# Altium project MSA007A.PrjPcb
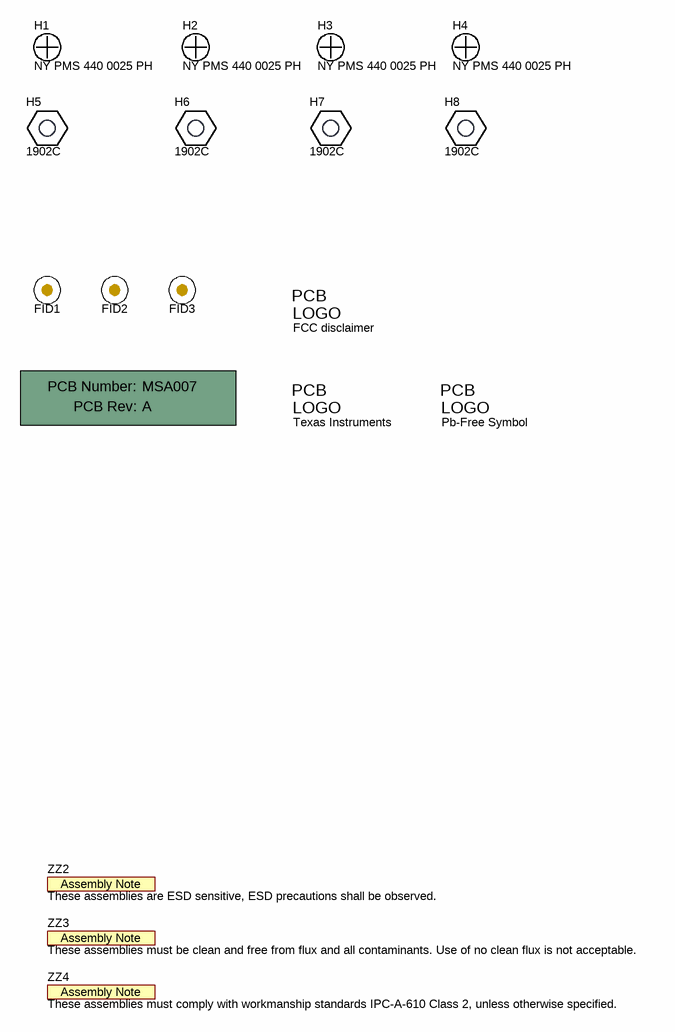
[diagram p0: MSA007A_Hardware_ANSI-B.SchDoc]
CopyrightYear: 2015; PCB_Layout: Alex Wang; PCB_Rev: A; PRJ_Customer: Public Release; PRJ_Engineer: Alex Wang; PRJ_Number: MSA007; PRJ_Title: TPS4H160EVM; SCH_Rev: A; TechSupport: http://www.ti.com/support
2 sheets, 129 parts. Net scope: global (net labels, ports and power ports of the same name join across sheets).
Board file: MSA007A.PcbDoc
Sheets:
  MSA007A_Hardware_ANSI-B.SchDoc
  MSA007A.SchDoc

## Sheet MSA007A_Hardware_ANSI-B.SchDoc
size 431 x 279 mm; Date: Not shown in title block; ApprovedBy: Not shown in title block; CheckedBy: Not shown in title block; Author: Not shown in title block; CompanyName: Not shown in title block; Engineer: Not shown in title block; Organization: Not shown in title block; Address1: Not shown in title block; Address2: Not shown in title block; Address3: Not shown in title block; Address4: Not shown in title block; DocumentNumber: 1; Revision: Use project parameter SCH_Rev; SheetNumber: 1; SheetTotal: 1; PageSetup: Record=PageOptions¦CenterHorizontal=True¦CenterVertical=True¦PrintScale=1.00¦XCorrection=1.00¦YCorrection=1.00¦PrintKind=0¦BorderSize=5000000¦LeftOffset=0¦BottomOffset=0¦Orientation=2¦PaperLength=1000¦PaperWidth=1000¦Scale=100¦PaperSource=15¦PrintQuality=600¦MediaType=1¦DitherType=10¦PaperKind=Letter¦PrintScaleMode=1

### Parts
!PCB1  Printed Circuit Board  (value not drawn)  (mechanical)
FID1  Fiducial  [Fiducial10-20]  (value not drawn)
FID2  Fiducial  [Fiducial10-20]  (value not drawn)
FID3  Fiducial  [Fiducial10-20]  (value not drawn)
H1  NY PMS 440 0025 PH  [NY PMS 440 0025 PH]
H2  NY PMS 440 0025 PH  [NY PMS 440 0025 PH]
H3  NY PMS 440 0025 PH  [NY PMS 440 0025 PH]
H4  NY PMS 440 0025 PH  [NY PMS 440 0025 PH]
H5  1902C  [Keystone_1902C]
H6  1902C  [Keystone_1902C]
H7  1902C  [Keystone_1902C]
H8  1902C  [Keystone_1902C]
Logo1  Texas Instruments  [TI_Stacked_Overlay_Medium]  (no BOM)
Logo2  Pb-Free Symbol  [Pb-Free_Overlay_Small]  (no BOM)
Logo3  FCC disclaimer  [FCC_disclaimer]  (no BOM)
ZZ2  These assemblies are ESD sensitive, ESD precautions shall be observed.  [AssemblyNote]  (no BOM)
ZZ3  These assemblies must be clean and free from flux and all contaminants. Use of no clean flux is not acceptable.  [AssemblyNote]  (no BOM)
ZZ4  These assemblies must comply with workmanship standards IPC-A-610 Class 2, unless otherwise specified.  [AssemblyNote]  (no BOM)

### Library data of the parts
!PCB1 = PCB: Manufacturer: Any; PartNumber: MSA007; SymbolCreator: a0412235
FID1-FID3 = Fiducial: Fiducial mark.  There is nothing to buy or mount.; SymbolCreator: codlsc
H1-H4 = NY PMS 440 0025 PH: Machine Screw, Round, #4-40 x 1/4, Nylon, Philips panhead; Manufacturer: B&F Fastener Supply; CompType: Hardware; SymbolCreator: codlsc; U/M: EA
H5-H8 = 1902C: Standoff, Hex, 0.5"L #4-40 Nylon; Manufacturer: Keystone; CompType: Hardware; SymbolCreator: a0412235
Logo1 = TI_Logo: Texas Instrument Corporate Signature; SymbolCreator: a0412235
Logo2 = Pb-Free: SymbolCreator: a0412235
Logo3 = FCC_disclaimer: SymbolCreator: codlsc
ZZ2-ZZ4 = AssemblyNote: SymbolCreator: codlsc

## Sheet MSA007A.SchDoc
size A2; Date: Not shown in title block; ApprovedBy: Not shown in title block; CheckedBy: Not shown in title block; Author: Not shown in title block; CompanyName: Not shown in title block; DrawnBy: Alex Wang; Engineer: Not shown in title block; Organization: Not shown in title block; Address1: Not shown in title block; Address2: Not shown in title block; Address3: Not shown in title block; Address4: Not shown in title block; DocumentNumber: 1; Revision: Use project parameter SCH_Rev; SheetNumber: 1; SheetTotal: 1; PageSetup: Record=PageOptions¦CenterHorizontal=True¦CenterVertical=True¦PrintScale=0.47¦XCorrection=1.00¦YCorrection=1.00¦PrintKind=0¦BorderSize=5000000¦LeftOffset=0¦BottomOffset=0¦Orientation=2¦PaperLength=1000¦PaperWidth=1000¦Scale=100¦PaperSource=15¦PrintQuality=600¦MediaType=1¦DitherType=10¦PaperKind=Letter¦PrintScaleMode=1
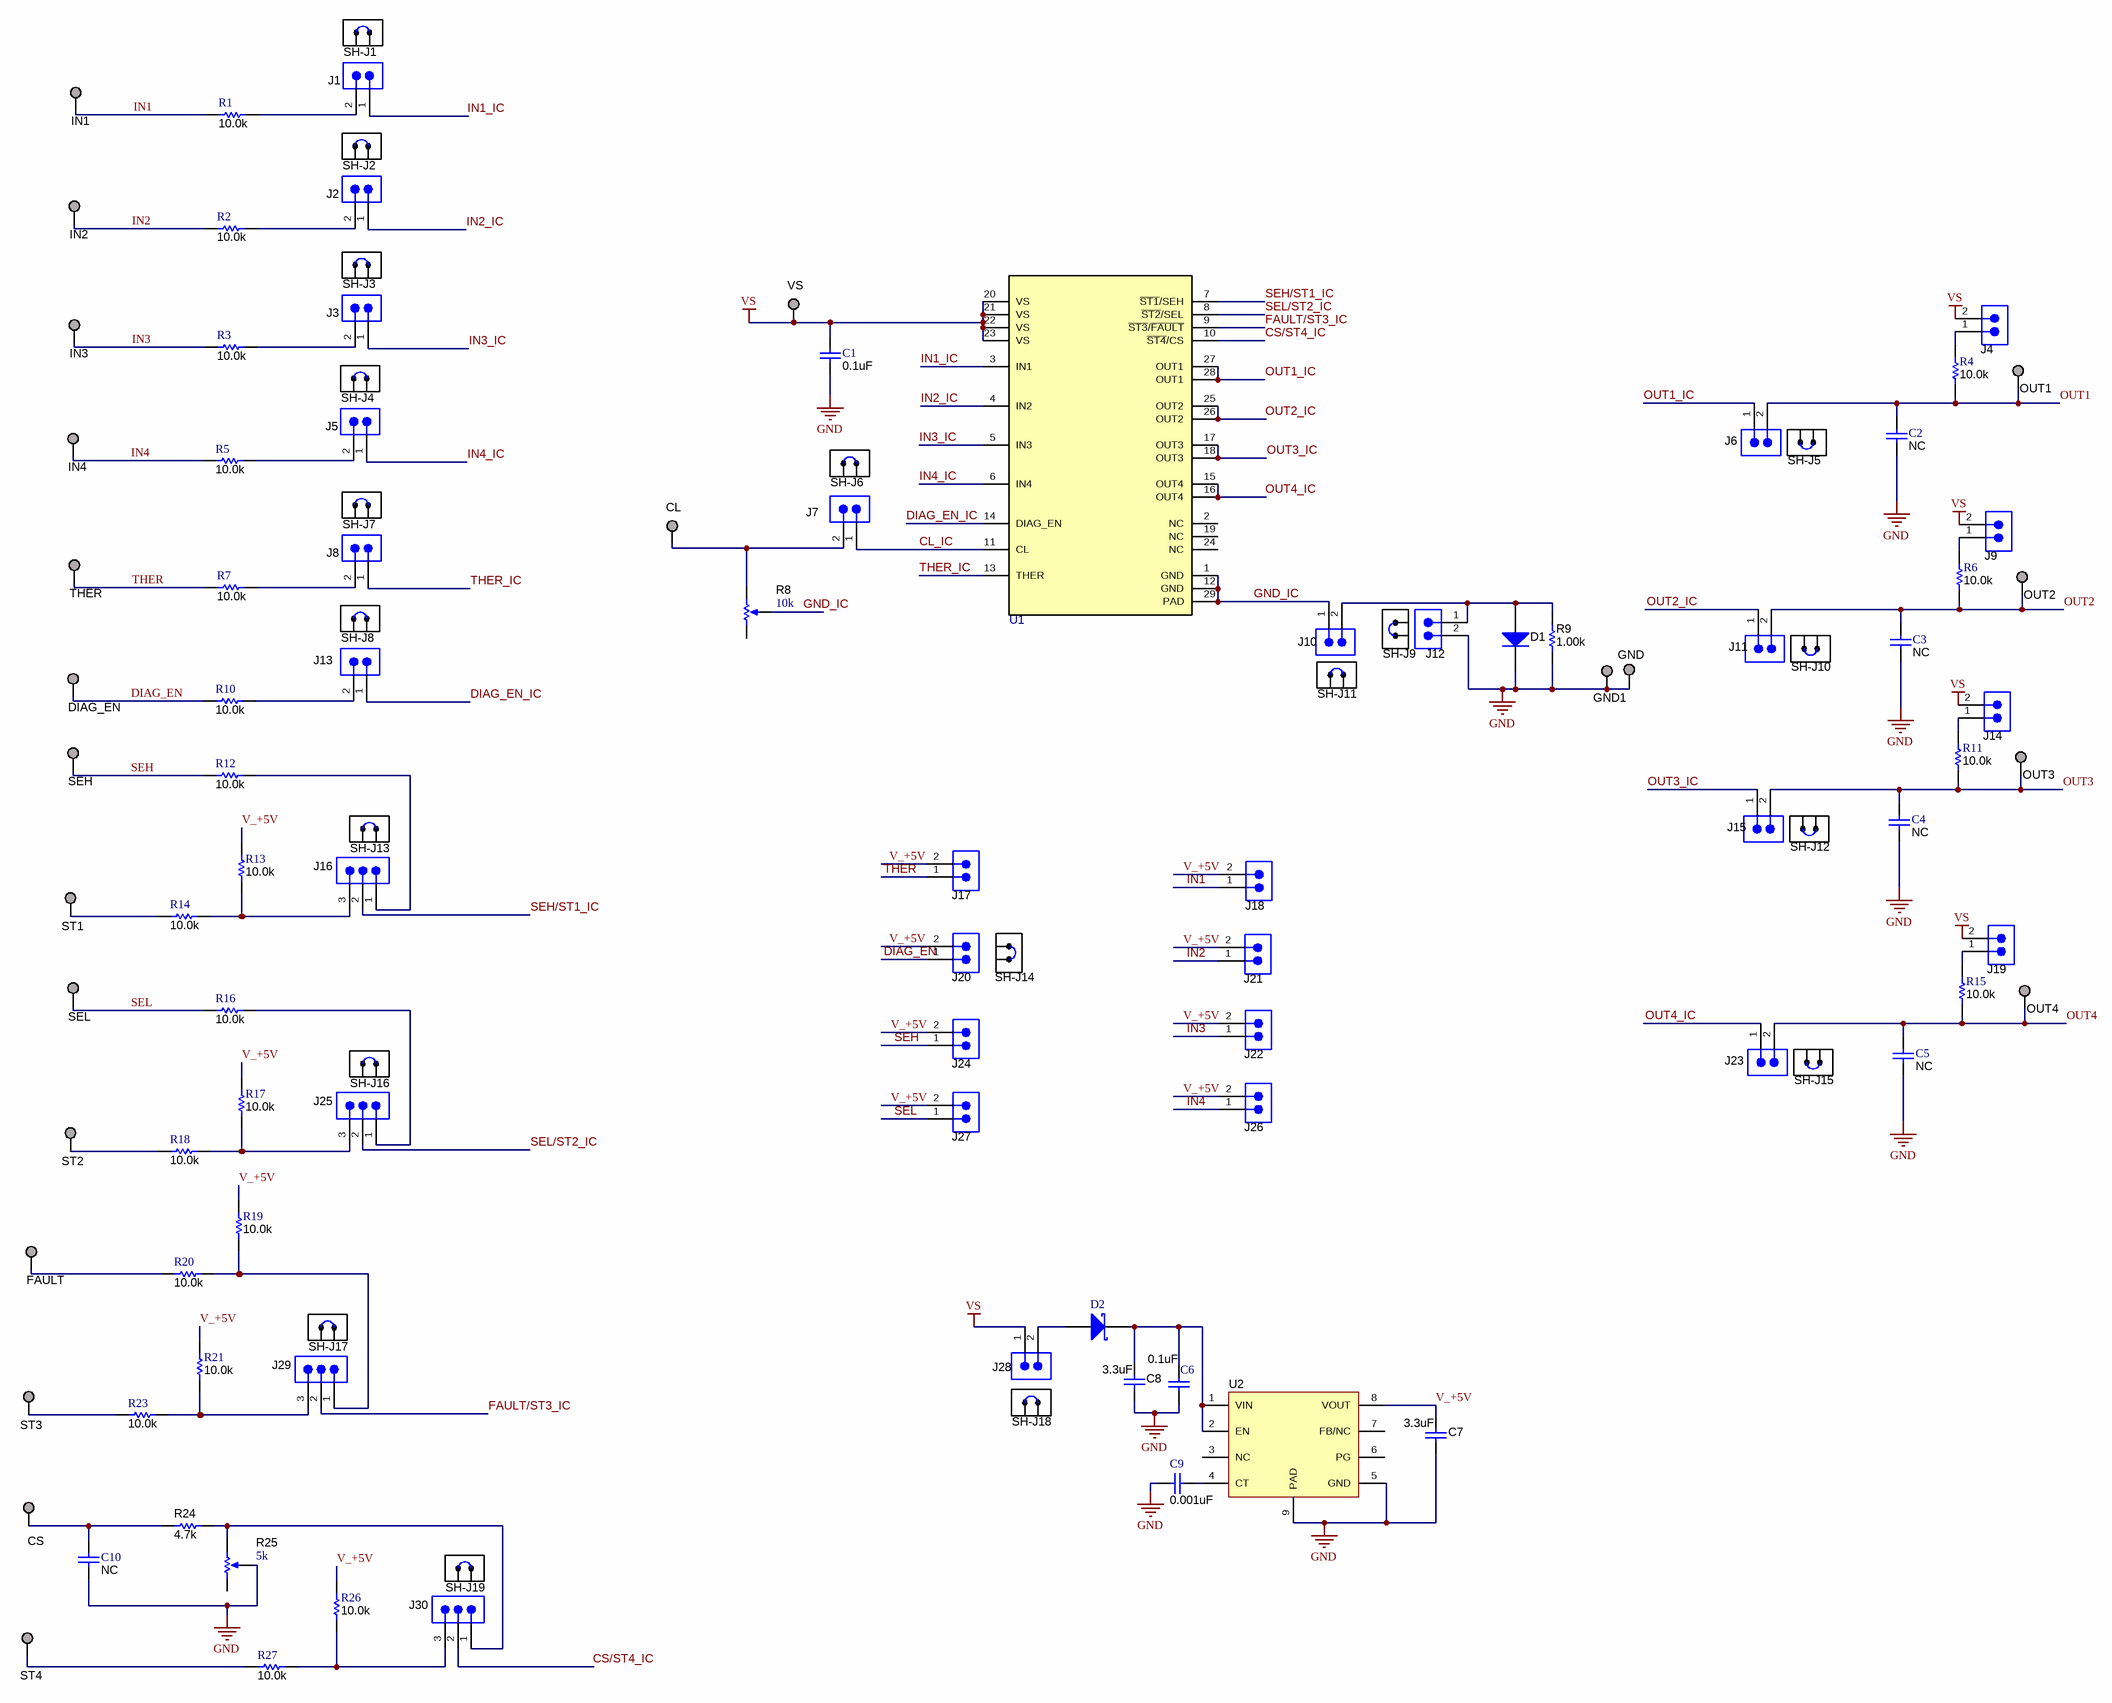
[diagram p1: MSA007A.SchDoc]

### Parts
C1  ValueDisplayed: 0.1uF  [0603]  (hidden comment: GRM188R71H104KA93D)
C2  08051C103JAT2A  [0805_HV]  (value not drawn)
C3  08051C103JAT2A  [0805_HV]  (value not drawn)
C4  08051C103JAT2A  [0805_HV]  (value not drawn)
C5  08051C103JAT2A  [0805_HV]  (value not drawn)
C6  ValueDisplayed: 0.1uF  [0603]  (hidden comment: GRM188R71H104KA93D)
C7  ValueDisplayed: 3.3uF  [1210]  (hidden comment: C3225X7R1H335M)
C8  ValueDisplayed: 3.3uF  [1210]  (hidden comment: C3225X7R1H335M)
C9  ValueDisplayed: 0.001uF  [0603]  (hidden comment: 06035A102KAT2A)
C10  ValueDisplayed: NC  [0603]  (hidden comment: GRM188R71H104KA93D)
CL  Suggest using a net name here  [Keystone1502-2]  (value not drawn)
CS  Suggest using a net name here  [Keystone1502-2]  (value not drawn)
D1  BAS21-7-F  [SOT-23]  (value not drawn)
D2  B150-13-F  [SMA]  (value not drawn)
DIAG_EN  Suggest using a net name here  [Keystone1502-2]  (value not drawn)
FAULT  Suggest using a net name here  [Keystone1502-2]  (value not drawn)
GND  Suggest using a net name here  [Keystone1502-2]  (value not drawn)
GND1  GND  [Keystone1502-2]  (value not drawn)
IN1  Suggest using a net name here  [Keystone1502-2]  (value not drawn)
IN2  Suggest using a net name here  [Keystone1502-2]  (value not drawn)
IN3  Suggest using a net name here  [Keystone1502-2]  (value not drawn)
IN4  Suggest using a net name here  [Keystone1502-2]  (value not drawn)
J1  TSW-102-07-G-S  [TSW-102-07-G-S]  (value not drawn)
J2  TSW-102-07-G-S  [TSW-102-07-G-S]  (value not drawn)
J3  TSW-102-07-G-S  [TSW-102-07-G-S]  (value not drawn)
J4  TSW-102-07-G-S  [TSW-102-07-G-S]  (value not drawn)
J5  TSW-102-07-G-S  [TSW-102-07-G-S]  (value not drawn)
J6  TSW-102-07-G-S  [TSW-102-07-G-S]  (value not drawn)
J7  TSW-102-07-G-S  [TSW-102-07-G-S]  (value not drawn)
J8  TSW-102-07-G-S  [TSW-102-07-G-S]  (value not drawn)
J9  TSW-102-07-G-S  [TSW-102-07-G-S]  (value not drawn)
J10  TSW-102-07-G-S  [TSW-102-07-G-S]  (value not drawn)
J11  TSW-102-07-G-S  [TSW-102-07-G-S]  (value not drawn)
J12  TSW-102-07-G-S  [TSW-102-07-G-S]  (value not drawn)
J13  TSW-102-07-G-S  [TSW-102-07-G-S]  (value not drawn)
J14  TSW-102-07-G-S  [TSW-102-07-G-S]  (value not drawn)
J15  TSW-102-07-G-S  [TSW-102-07-G-S]  (value not drawn)
J16  TSW-103-07-G-S  [TSW-103-07-G-S]  (value not drawn)
J17  TSW-102-07-G-S  [TSW-102-07-G-S]  (value not drawn)
J18  TSW-102-07-G-S  [TSW-102-07-G-S]  (value not drawn)
J19  TSW-102-07-G-S  [TSW-102-07-G-S]  (value not drawn)
J20  TSW-102-07-G-S  [TSW-102-07-G-S]  (value not drawn)
J21  TSW-102-07-G-S  [TSW-102-07-G-S]  (value not drawn)
J22  TSW-102-07-G-S  [TSW-102-07-G-S]  (value not drawn)
J23  TSW-102-07-G-S  [TSW-102-07-G-S]  (value not drawn)
J24  TSW-102-07-G-S  [TSW-102-07-G-S]  (value not drawn)
J25  TSW-103-07-G-S  [TSW-103-07-G-S]  (value not drawn)
J26  TSW-102-07-G-S  [TSW-102-07-G-S]  (value not drawn)
J27  TSW-102-07-G-S  [TSW-102-07-G-S]  (value not drawn)
J28  TSW-102-07-G-S  [TSW-102-07-G-S]  (value not drawn)
J29  TSW-103-07-G-S  [TSW-103-07-G-S]  (value not drawn)
J30  TSW-103-07-G-S  [TSW-103-07-G-S]  (value not drawn)
OUT1  Suggest using a net name here  [Keystone1502-2]  (value not drawn)
OUT2  Suggest using a net name here  [Keystone1502-2]  (value not drawn)
OUT3  Suggest using a net name here  [Keystone1502-2]  (value not drawn)
OUT4  Suggest using a net name here  [Keystone1502-2]  (value not drawn)
R1  value 10.0k  [0603]  (hidden comment: CRCW060310K0FKEA)
R2  value 10.0k  [0603]  (hidden comment: CRCW060310K0FKEA)
R3  value 10.0k  [0603]  (hidden comment: CRCW060310K0FKEA)
R4  value 10.0k  [0603]  (hidden comment: CRCW060310K0FKEA)
R5  value 10.0k  [0603]  (hidden comment: CRCW060310K0FKEA)
R6  value 10.0k  [0603]  (hidden comment: CRCW060310K0FKEA)
R7  value 10.0k  [0603]  (hidden comment: CRCW060310K0FKEA)
R8  value 10k  [BOURNS_3386P]  (hidden comment: 3386P-1-103LF)
R9  value 1.00k  [0805_HV]  (hidden comment: CRCW08051K00FKEA)
R10  value 10.0k  [0603]  (hidden comment: CRCW060310K0FKEA)
R11  value 10.0k  [0603]  (hidden comment: CRCW060310K0FKEA)
R12  value 10.0k  [0603]  (hidden comment: CRCW060310K0FKEA)
R13  value 10.0k  [0603]  (hidden comment: CRCW060310K0FKEA)
R14  value 10.0k  [0603]  (hidden comment: CRCW060310K0FKEA)
R15  value 10.0k  [0603]  (hidden comment: CRCW060310K0FKEA)
R16  value 10.0k  [0603]  (hidden comment: CRCW060310K0FKEA)
R17  value 10.0k  [0603]  (hidden comment: CRCW060310K0FKEA)
R18  value 10.0k  [0603]  (hidden comment: CRCW060310K0FKEA)
R19  value 10.0k  [0603]  (hidden comment: CRCW060310K0FKEA)
R20  value 10.0k  [0603]  (hidden comment: CRCW060310K0FKEA)
R21  value 10.0k  [0603]  (hidden comment: CRCW060310K0FKEA)
R23  value 10.0k  [0603]  (hidden comment: CRCW060310K0FKEA)
R24  value 4.7k  [0603]  (hidden comment: CRCW06034K70JNEA)
R25  value 5k  [BOURNS_3386P]  (hidden comment: 3386P-1-502LF)
R26  value 10.0k  [0603]  (hidden comment: CRCW060310K0FKEA)
R27  value 10.0k  [0603]  (hidden comment: CRCW060310K0FKEA)
SEH  Suggest using a net name here  [Keystone1502-2]  (value not drawn)
SEL  Suggest using a net name here  [Keystone1502-2]  (value not drawn)
SH-J1  969102-0000-DA  [SNT-100-BK-G]  (value not drawn)
SH-J2  969102-0000-DA  [SNT-100-BK-G]  (value not drawn)
SH-J3  969102-0000-DA  [SNT-100-BK-G]  (value not drawn)
SH-J4  969102-0000-DA  [SNT-100-BK-G]  (value not drawn)
SH-J5  969102-0000-DA  [SNT-100-BK-G]  (value not drawn)
SH-J6  969102-0000-DA  [SNT-100-BK-G]  (value not drawn)
SH-J7  969102-0000-DA  [SNT-100-BK-G]  (value not drawn)
SH-J8  969102-0000-DA  [SNT-100-BK-G]  (value not drawn)
SH-J9  969102-0000-DA  [SNT-100-BK-G]  (value not drawn)
SH-J10  969102-0000-DA  [SNT-100-BK-G]  (value not drawn)
SH-J11  969102-0000-DA  [SNT-100-BK-G]  (value not drawn)
SH-J12  969102-0000-DA  [SNT-100-BK-G]  (value not drawn)
SH-J13  969102-0000-DA  [SNT-100-BK-G]  (value not drawn)
SH-J14  969102-0000-DA  [SNT-100-BK-G]  (value not drawn)
SH-J15  969102-0000-DA  [SNT-100-BK-G]  (value not drawn)
SH-J16  969102-0000-DA  [SNT-100-BK-G]  (value not drawn)
SH-J17  969102-0000-DA  [SNT-100-BK-G]  (value not drawn)
SH-J18  969102-0000-DA  [SNT-100-BK-G]  (value not drawn)
SH-J19  969102-0000-DA  [SNT-100-BK-G]  (value not drawn)
ST1  Suggest using a net name here  [Keystone1502-2]  (value not drawn)
ST2  Suggest using a net name here  [Keystone1502-2]  (value not drawn)
ST3  Suggest using a net name here  [Keystone1502-2]  (value not drawn)
ST4  Suggest using a net name here  [Keystone1502-2]  (value not drawn)
THER  Suggest using a net name here  [Keystone1502-2]  (value not drawn)
U1  TPS4H160BQPWPRQ1  [PWP0028C_N]  (value not drawn)
U2  TPS7A6650QDGNRQ1  [DGN0008D_N]  (value not drawn)
VS  Suggest using a net name here  [Keystone1502-2]  (value not drawn)

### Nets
GND: C1.1 C2.2 C3.2 C4.2 C5.2 C6.1 C7.2 C8.2 C9.1 C10.2 D1.3(K) GND.1 GND1.1 J12.2 R9.2 R25.2(WIPER) U2.5(GND) U2.9(PAD)
VS: C1.2 J4.2 J9.2 J14.2 J19.2 J28.1 U1.20(VS) U1.21(VS) U1.22(VS) U1.23(VS) VS.1
CL_IC: J7.1 U1.11(CL)
CS/ST4_IC: J30.2 U1.10(~{ST4}/CS)
DIAG_EN: DIAG_EN.1 J20.1 R10.2
DIAG_EN_IC: J13.1 U1.14(DIAG_EN)
FAULT/ST3_IC: J29.2 U1.9(~{ST3}/~{FAULT})
GND_IC: J10.1 R8.2(WIPER) U1.1(GND) U1.12(GND) U1.29(PAD)
IN1: IN1.1 J18.1 R1.2
IN1_IC: J1.1 U1.3(IN1)
IN2: IN2.1 J21.1 R2.2
IN2_IC: J2.1 U1.4(IN2)
IN3: IN3.1 J22.1 R3.2
IN3_IC: J3.1 U1.5(IN3)
IN4: IN4.1 J26.1 R5.2
IN4_IC: J5.1 U1.6(IN4)
OUT1: C2.1 J6.2 OUT1.1 R4.1
OUT1_IC: J6.1 U1.27(OUT1) U1.28(OUT1)
OUT2: C3.1 J11.2 OUT2.1 R6.1
OUT2_IC: J11.1 U1.25(OUT2) U1.26(OUT2)
OUT3: C4.1 J15.2 OUT3.1 R11.1
OUT3_IC: J15.1 U1.17(OUT3) U1.18(OUT3)
OUT4: C5.1 J23.2 OUT4.1 R15.1
OUT4_IC: J23.1 U1.15(OUT4) U1.16(OUT4)
SEH: J24.1 R12.2 SEH.1
SEH/ST1_IC: J16.2 U1.7(~{ST1}/SEH)
SEL: J27.1 R16.2 SEL.1
SEL/ST2_IC: J25.2 U1.8(~{ST2}/SEL)
THER: J17.1 R7.2 THER.1
THER_IC: J8.1 U1.13(THER)
V_+5V: C7.1 J17.2 J18.2 J20.2 J21.2 J22.2 J24.2 J26.2 J27.2 R13.1 R17.1 R19.1 R21.1 R26.1 U2.8(VOUT)
NetC6_2: C6.2 C8.1 D2.1(K) U2.1(VIN) U2.2(EN)
NetC9_2: C9.2 U2.4(CT)
NetC10_1: C10.1 CS.1 R24.2
NetCL_1: CL.1 J7.2 R8.3(CW)
NetD1_1: D1.1(A) J10.2 J12.1 R9.1
NetD2_2: D2.2(A) J28.2
NetFAULT_1: FAULT.1 R20.2
NetJ1_2: J1.2 R1.1
NetJ2_2: J2.2 R2.1
NetJ3_2: J3.2 R3.1
NetJ4_1: J4.1 R4.2
NetJ5_2: J5.2 R5.1
NetJ8_2: J8.2 R7.1
NetJ9_1: J9.1 R6.2
NetJ13_2: J13.2 R10.1
NetJ14_1: J14.1 R11.2
NetJ16_1: J16.1 R12.1
NetJ16_3: J16.3 R13.2 R14.2
NetJ19_1: J19.1 R15.2
NetJ25_1: J25.1 R16.1
NetJ25_3: J25.3 R17.2 R18.2
NetJ29_1: J29.1 R19.2 R20.1
NetJ29_3: J29.3 R21.2 R23.2
NetJ30_1: J30.1 R24.1 R25.3(CW)
NetJ30_3: J30.3 R26.2 R27.2
NetR14_1: R14.1 ST1.1
NetR18_1: R18.1 ST2.1
NetR23_1: R23.1 ST3.1
NetR27_1: R27.1 ST4.1

Not connected (* = marked no-connect by the designer): R8 1(CCW); R25 1(CCW); U1 2(NC) 19(NC) 24(NC); U2 3(NC) 6(PG) 7(FB/NC)

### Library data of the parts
C1 C6 C10 = GRM188R71H104KA93D: CAP, CERM, 0.1uF, 50V, +/-10%, X7R, 0603; Manufacturer: MuRata; Polarized: N; CompType: Capacitor; U/M: EA; Cap_F: 0.0000001; Tolerance_%: 10; VDC_V: 50; TaMin_C: -55; TaMax_C: 125
C2-C5 = 08051C103JAT2A: NC; Manufacturer: AVX; Polarized: N; CompType: Capacitor; Value: 0.01uF; U/M: EA; Cap_F: 0.00000001; Tolerance_%: 5; ESR_Ohm: 0.078; Value1: 0.078 ohm; VDC_V: 100; Value2: 100V; TempCo: X7R; TaMin_C: -55; TaMax_C: 125; Cap_Case: 0805
C7 C8 = C3225X7R1H335M: CAP, CERM, 3.3uF, 50V, +/-20%, X7R, 1210; Manufacturer: TDK; Polarized: N; CompType: Capacitor; U/M: EA; Cap_F: 0.0000033; Tolerance_%: 20; VDC_V: 50; TaMin_C: -55; TaMax_C: 125
C9 = 06035A102KAT2A: CAP, CERM, 1000pF, 50V, +/-10%, C0G/NP0, 0603; Manufacturer: AVX; Polarized: N; CompType: Capacitor; U/M: EA; Cap_F: 0.000000001; Tolerance_%: 10; ESR_Ohm: 0.048; Value1: 0.048 ohm; VDC_V: 50; TaMin_C: -55; TaMax_C: 125
CL CS DIAG_EN FAULT GND GND1 IN1-IN4 OUT1-OUT4 SEH SEL ST1-ST4 THER VS = 1502-2: Terminal, Turret, TH, Double; Manufacturer: Keystone; CompType: Turret Terminal; U/M: EA
D1 = BAS21-7-F: Diode, Switching, 200V, 0.2A, SOT-23; Manufacturer: Diodes Inc.; U/M: EA; Vf_V: 1.25; Value2: 1.25V; Io_A: 0.2; Vr_V: 200; TJmax_C: 150; RJC_CperW: 500
D2 = B150-13-F: Diode, Schottky, 50V, 1A, SMA; Manufacturer: Diodes Inc.; Alternate Manufacturer: Any; Alternate PartNumber: Equivalent; Value: 0.7V; U/M: EA; Vf_V: 0.7; Io_A: 1; Vr_V: 50; TJmax_C: 150; RJC_CperW: 20
J1-J15 J17-J24 J26-J28 = TSW-102-07-G-S: Header, TH, 100mil, 2x1, Gold plated, 230 mil above insulator; Manufacturer: Samtec, Inc.; Alternate Manufacturer: Any; Alternate PartNumber: Equivalent; U/M: EA
J16 J25 J29 J30 = TSW-103-07-G-S: Header, TH, 100mil, 3x1, Gold plated, 230 mil above insulator; Manufacturer: Samtec, Inc.; SymbolCreator: a0799628; U/M: EA
R1-R7 R10-R21 R23 R26 R27 = CRCW060310K0FKEA: RES, 10.0k ohm, 1%, 0.1W, 0603; Manufacturer: Vishay-Dale; CompType: Resistor; Res_ohm: 10000; Value_Code: 10k0; Tolerance_%: 1; Power_W: 0.1; VDC_V: 75; TempCo: 100 ppm/C; EIA_Code: E96; U/M: EA
R8 = 3386P-1-103LF: TRIMMER, 10k ohm, 0.5W, TH; Manufacturer: Bourns; Sim Note: Enter the Resistance value and the set point into parameter fields.; SymbolCreator: a0412235
R9 = CRCW08051K00FKEA: RES, 1.00k ohm, 1%, 0.125W, 0805; Manufacturer: Vishay-Dale; CompType: Resistor; Res_ohm: 1000; Value_Code: 1k00; Tolerance_%: 1; Power_W: 0.125; VDC_V: 150; TempCo: 100 ppm/C; EIA_Code: E96; U/M: EA
R24 = CRCW06034K70JNEA: RES, 4.7k ohm, 5%, 0.1W, 0603; Manufacturer: Vishay-Dale; CompType: Resistor; Res_ohm: 4700; Value_Code: 4k70; Tolerance_%: 5; Power_W: 0.1; VDC_V: 75; TempCo: 200 ppm/C; EIA_Code: E24; U/M: EA
R25 = 3386P-1-502LF: TRIMMER, 5k ohm, 0.5W, TH; Manufacturer: Bourns; Sim Note: Enter the Resistance value and the set point into parameter fields.; SymbolCreator: a0412235
SH-J1-SH-J19 = 969102-0000-DA: Shunt, 100mil, Gold plated, Black; Manufacturer: 3M; Alternate Manufacturer: Samtec; Value: 1x2; Note: You can "mate" this to a header by matching the designator.  i.e. use SH-J3 for header J3
U1 = TPS4H160BQPWPRQ1: 40V/140mohm Quad Channels Smart High Side Power Switch, PWP0028C; Manufacturer: Texas Instruments; SymbolCreator: Altium; CompType: IC; U/M: EA
U2 = TPS7A6650QDGNRQ1: High-Voltage Ultralow-Iq Low-Dropout Regulator, DGN0008D; Alternate Manufacturer: None; Manufacturer: Texas Instruments; SymbolCreator: a0411947; CompType: IC; U/M: EA

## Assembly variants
-001: not fitted C2 C3 C4 C5 C10 FID1 FID2 FID3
